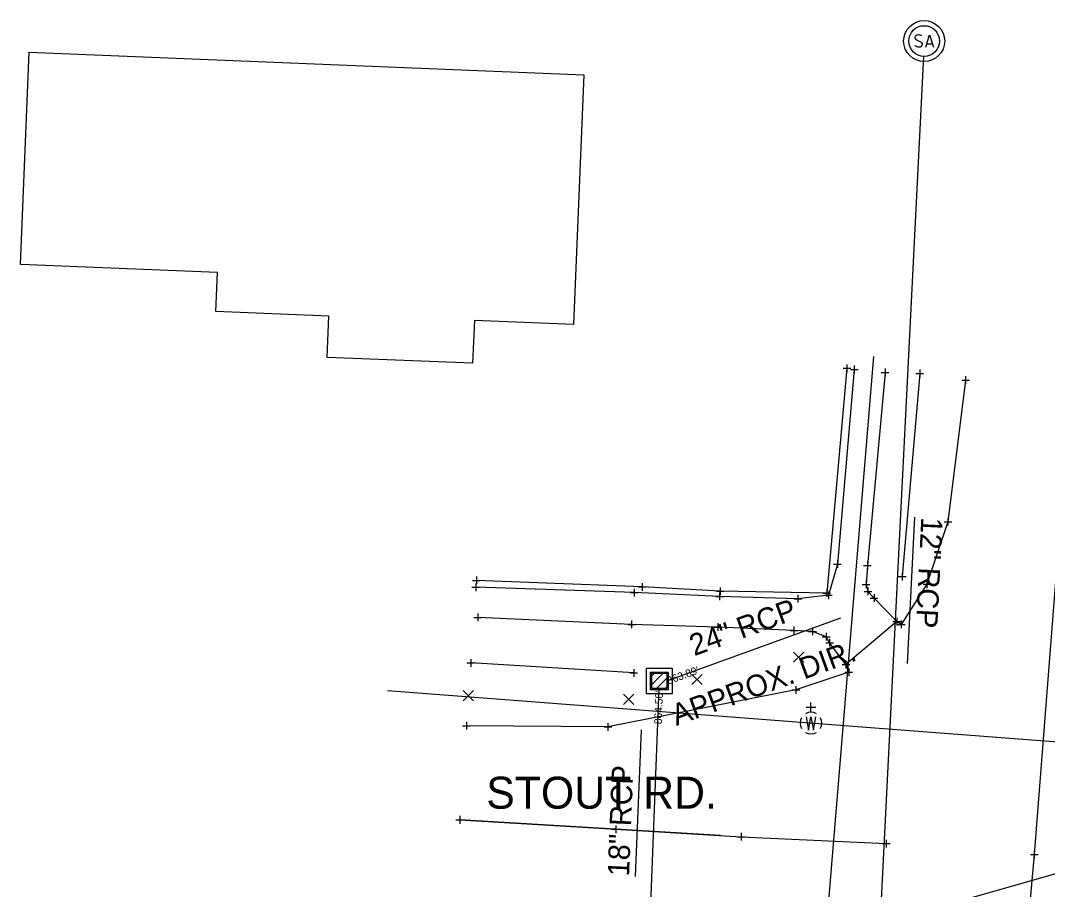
# Model space of a CAD drawing. Extents: x 1380440 to 1381945, y 468756 to 470369.
# Drawn here: x 1381490.3 to 1381624.1, y 470255.4 to 470368.5 of the extents above; entities that cross this region are included whole.
import ezdxf

# ---------------------------------------------------------------- set-up
doc = ezdxf.new("R2010")
doc.units = 0
for name, color, linetype in [('BD_X_Building', 7, 'Continuous'), ('DR_P_Headwall', 7, 'Continuous'), ('GE_P_Driveway_CL', 7, 'Continuous'), ('GK_Drainage_Nodes', 7, 'Continuous'), ('PM_X_CL_Double_Solid', 7, 'Continuous'), ('PM_X_Crosswalk', 7, 'Continuous'), ('PV_P_Curb', 7, 'Continuous'), ('PV_P_Curb_Ramp', 7, 'Continuous'), ('PV_P_EOP', 7, 'Continuous'), ('PV_P_Joint', 7, 'Continuous'), ('RW_P_Const_Limits', 7, 'Continuous'), ('RW_P_Esmt_TMP', 7, 'Continuous'), ('RW_X_CL', 7, 'Continuous'), ('SC_Scratch1', 7, 'Continuous'), ('SC_Shading1', 7, 'Continuous'), ('SH_Named_Boundary', 7, 'Continuous'), ('UT_X_Gas', 7, 'Continuous'), ('UT_X_Sanitary_Line', 7, 'Continuous'), ('UT_X_Sanitary_Text', 7, 'Continuous'), ('UT_X_Water', 7, 'Continuous'), ('X-CL', 7, 'Continuous'), ('X-SUBDIVISION', 7, 'Continuous')]:
    doc.layers.add(name, color=color, linetype=linetype)

msp = doc.modelspace()

# ---------------------------------------------------------------- linework, layer by layer
at = {"layer": 'BD_X_Building'}
msp.add_lwpolyline([(1381490.34, 470336.77), (1381491.47, 470364.43), (1381563.68, 470361.48), (1381562.35, 470328.97), (1381549.43, 470329.5), (1381549.2, 470323.92), (1381530.28, 470324.69), (1381530.5, 470330.07), (1381515.76, 470330.67), (1381515.97, 470335.73)], close=True, dxfattribs=at)
at = {"layer": 'DR_P_Headwall'}
for points in [[(1381598.9, 470323.13), (1381596.7, 470297.78), (1381595.54, 470293.73), (1381591.57, 470293.27), (1381581.37, 470293.57), (1381570.24, 470294.06), (1381549.62, 470294.77)], [(1381602.92, 470322.73), (1381600.62, 470297.61), (1381600.44, 470295.13), (1381600.68, 470294.22), (1381601.47, 470293.36), (1381604.44, 470290.29), (1381597.81, 470284.69), (1381595.69, 470287.54), (1381595.24, 470288.31), (1381593.46, 470289.01), (1381591.05, 470289.15), (1381581.13, 470289.58), (1381569.91, 470289.93), (1381549.88, 470290.83)]]:
    msp.add_lwpolyline(points, dxfattribs=at)
at = {"layer": 'GE_P_Driveway_CL'}
for p, q in [((1381590.99, 470284.99), (1381592.32, 470286.32)), ((1381590.99, 470286.32), (1381592.32, 470284.99)), ((1381577.75, 470282.09), (1381579.09, 470283.42)), ((1381577.75, 470283.42), (1381579.09, 470282.09)), ((1381547.97, 470279.98), (1381549.3, 470281.31)), ((1381547.97, 470281.31), (1381549.3, 470279.98)), ((1381568.86, 470279.49), (1381570.2, 470280.83)), ((1381568.86, 470280.83), (1381570.2, 470279.49))]:
    msp.add_line(p, q, dxfattribs=at)
at = {"layer": 'GK_Drainage_Nodes'}
msp.add_lwpolyline([(1381597.94, 470323.28), (1381595.32, 470294.01), (1381581.44, 470294.24), (1381571.27, 470294.81), (1381549.69, 470295.66)], dxfattribs=at)
at = {"layer": 'PM_X_CL_Double_Solid'}
msp.add_line((1381581.5, 470262.44), (1381547.54, 470264.48), dxfattribs=at)
at = {"layer": 'PM_X_Crosswalk'}
msp.add_line((1381638.41, 470261.25), (1381586.42, 470246.45), dxfattribs=at)
at = {"layer": 'PV_P_Curb'}
for points in [[(1381607.42, 470322.6), (1381605.14, 470296.15)], [(1381570.18, 470283.61), (1381548.95, 470284.92)]]:
    msp.add_lwpolyline(points, dxfattribs=at)
at = {"layer": 'PV_P_Curb_Ramp'}
for p, q in [((1381608, 470367.88), (1381608, 470367.88)), ((1381608, 470365.88), (1381608, 470365.88)), ((1381608, 470365.88), (1381608, 470365.88)), ((1381608, 470365.88), (1381608, 470365.88)), ((1381608, 470363.88), (1381608, 470363.88)), ((1381573.51, 470284.22), (1381573.51, 470284.22)), ((1381573.51, 470283.56), (1381573.51, 470283.56)), ((1381572.52, 470282.56), (1381572.52, 470282.56)), ((1381573.51, 470282.56), (1381573.51, 470282.56)), ((1381573.51, 470282.56), (1381573.51, 470282.56)), ((1381573.51, 470282.56), (1381573.51, 470282.56)), ((1381574.51, 470282.56), (1381574.51, 470282.56)), ((1381573.51, 470281.56), (1381573.51, 470281.56)), ((1381573.51, 470280.89), (1381573.51, 470280.89))]:
    msp.add_line(p, q, dxfattribs=at)
msp.add_circle((1381608, 470365.88), 2, dxfattribs=at)
at = {"layer": 'PV_P_EOP'}
for points in [[(1381607.67, 470366.57), (1381607.64, 470366.59), (1381607.61, 470366.62), (1381607.49, 470366.66), (1381607.35, 470366.68), (1381607.25, 470366.68), (1381607.22, 470366.68), (1381607.05, 470366.65), (1381606.91, 470366.57), (1381606.83, 470366.47), (1381606.8, 470366.37), (1381606.8, 470366.29), (1381606.83, 470366.19), (1381606.93, 470366.1), (1381607.62, 470365.73), (1381607.68, 470365.68), (1381607.71, 470365.62), (1381607.73, 470365.55), (1381607.73, 470365.47), (1381607.72, 470365.4), (1381607.71, 470365.35), (1381607.68, 470365.28), (1381607.66, 470365.23), (1381607.63, 470365.2), (1381607.59, 470365.16), (1381607.56, 470365.13), (1381607.51, 470365.11), (1381607.47, 470365.1), (1381607.35, 470365.08), (1381607.18, 470365.08), (1381607.06, 470365.11), (1381606.9, 470365.2), (1381606.8, 470365.27)], [(1381608.21, 470365.08), (1381608.71, 470366.68), (1381609.21, 470365.08)], [(1381609.08, 470365.46), (1381608.34, 470365.46)]]:
    msp.add_lwpolyline(points, dxfattribs=at)
for radius in [2.67, 2]:
    msp.add_circle((1381608, 470365.88), radius, dxfattribs=at)
at = {"layer": 'PV_P_Joint'}
for p, q in [((1381572.37, 470281.94), (1381574.13, 470283.7)), ((1381572.37, 470283.07), (1381573, 470283.7)), ((1381572.97, 470281.41), (1381574.66, 470283.1)), ((1381574.1, 470281.41), (1381574.66, 470281.97))]:
    msp.add_line(p, q, dxfattribs=at)
for points in [[(1381571.85, 470284.22), (1381575.18, 470284.22), (1381575.18, 470280.89), (1381571.85, 470280.89)], [(1381572.37, 470283.7), (1381574.66, 470283.7), (1381574.66, 470281.41), (1381572.37, 470281.41)], [(1381572.52, 470283.56), (1381574.51, 470283.56), (1381574.51, 470281.56), (1381572.52, 470281.56)]]:
    msp.add_lwpolyline(points, close=True, dxfattribs=at)
at = {"layer": 'RW_P_Const_Limits'}
for p, q in [((1381593.9, 470279.11), (1381592.63, 470279.11)), ((1381593.26, 470278.48), (1381593.26, 470279.75)), ((1381593.26, 470277.08), (1381593.26, 470277.08))]:
    msp.add_line(p, q, dxfattribs=at)
msp.add_lwpolyline([(1381592.63, 470277.9), (1381592.94, 470276.17), (1381593.26, 470277.9), (1381593.58, 470276.17), (1381593.9, 470277.9)], dxfattribs=at)
for start, end in [(150.0184, 209.9816), (60.0184, 120.0157), (330.0184, 29.9816), (239.9843, 299.9816)]:
    msp.add_arc((1381593.26, 470277.08), 1.4, start, end, dxfattribs=at)
at = {"layer": 'RW_P_Esmt_TMP'}
msp.add_lwpolyline([(1381613.39, 470321.73), (1381611.1, 470303.3), (1381608.36, 470295.15), (1381605.01, 470289.92), (1381604.44, 470290.29), (1381597.81, 470284.69), (1381598.17, 470283.7), (1381591.29, 470281.39), (1381566.82, 470276.57), (1381548.39, 470276.73)], dxfattribs=at)
at = {"layer": 'RW_X_CL'}
for p, q in [((1381605.85, 470284.84), (1381606.8, 470303.9)), ((1381571.15, 470276.19), (1381570.39, 470257.11))]:
    msp.add_line(p, q, dxfattribs=at)
at = {"layer": 'SC_Shading1'}
for points in [[(1381627.41, 470324.23), (1381625.02, 470294.42), (1381622.34, 470259.95), (1381618.76, 470220.14), (1381616.92, 470200.19), (1381615.1, 470178.83), (1381610.95, 470124.78), (1381606.49, 470071.23), (1381602.26, 470019.36), (1381598.18, 469969.8), (1381595.01, 469928.06), (1381590.91, 469878.81), (1381589.36, 469859.11), (1381585.99, 469815.58)], [(1381547.54, 470264.48), (1381567.85, 470263.26), (1381584.18, 470262.28), (1381603.07, 470261.39)]]:
    msp.add_lwpolyline(points, dxfattribs=at)
at = {"layer": 'SH_Named_Boundary'}
for p, q in [((1381597.44, 470323.28), (1381598.44, 470323.28)), ((1381597.94, 470323.78), (1381597.94, 470322.78)), ((1381597.94, 470323.28), (1381597.94, 470323.28)), ((1381598.9, 470323.63), (1381598.9, 470322.63)), ((1381598.4, 470323.13), (1381599.4, 470323.13)), ((1381598.9, 470323.13), (1381598.9, 470323.13)), ((1381602.42, 470322.73), (1381603.42, 470322.73)), ((1381602.92, 470323.23), (1381602.92, 470322.23)), ((1381602.92, 470322.73), (1381602.92, 470322.73)), ((1381606.92, 470322.6), (1381607.92, 470322.6)), ((1381607.42, 470323.1), (1381607.42, 470322.1)), ((1381607.42, 470322.6), (1381607.42, 470322.6)), ((1381613.39, 470322.23), (1381613.39, 470321.23)), ((1381612.89, 470321.73), (1381613.89, 470321.73)), ((1381613.39, 470321.73), (1381613.39, 470321.73)), ((1381610.6, 470303.3), (1381611.6, 470303.3)), ((1381610.6, 470303.3), (1381611.6, 470303.3)), ((1381611.1, 470303.8), (1381611.1, 470302.8)), ((1381611.1, 470303.8), (1381611.1, 470302.8)), ((1381611.1, 470303.3), (1381611.1, 470303.3)), ((1381611.1, 470303.3), (1381611.1, 470303.3)), ((1381596.7, 470298.28), (1381596.7, 470297.28)), ((1381596.7, 470298.28), (1381596.7, 470297.28)), ((1381600.62, 470298.11), (1381600.62, 470297.11)), ((1381596.2, 470297.78), (1381597.2, 470297.78)), ((1381596.2, 470297.78), (1381597.2, 470297.78)), ((1381596.7, 470297.78), (1381596.7, 470297.78)), ((1381596.7, 470297.78), (1381596.7, 470297.78)), ((1381600.12, 470297.61), (1381601.12, 470297.61)), ((1381600.62, 470297.61), (1381600.62, 470297.61)), ((1381605.14, 470296.65), (1381605.14, 470295.65)), ((1381549.19, 470295.66), (1381550.19, 470295.66)), ((1381549.62, 470295.27), (1381549.62, 470294.27)), ((1381549.69, 470296.16), (1381549.69, 470295.16)), ((1381549.69, 470295.66), (1381549.69, 470295.66)), ((1381571.27, 470295.31), (1381571.27, 470294.31)), ((1381600.44, 470295.63), (1381600.44, 470294.63)), ((1381600.44, 470295.63), (1381600.44, 470294.63)), ((1381604.64, 470296.15), (1381605.64, 470296.15)), ((1381605.14, 470296.15), (1381605.14, 470296.15)), ((1381608.36, 470295.65), (1381608.36, 470294.65)), ((1381549.12, 470294.77), (1381550.12, 470294.77)), ((1381549.62, 470294.77), (1381549.62, 470294.77)), ((1381569.74, 470294.06), (1381570.74, 470294.06)), ((1381570.24, 470294.56), (1381570.24, 470293.56)), ((1381570.24, 470294.06), (1381570.24, 470294.06)), ((1381570.77, 470294.81), (1381571.77, 470294.81)), ((1381571.27, 470294.81), (1381571.27, 470294.81)), ((1381580.94, 470294.24), (1381581.94, 470294.24)), ((1381581.37, 470294.07), (1381581.37, 470293.07)), ((1381581.44, 470294.74), (1381581.44, 470293.74)), ((1381581.44, 470294.24), (1381581.44, 470294.24)), ((1381594.82, 470294.01), (1381595.82, 470294.01)), ((1381595.32, 470294.51), (1381595.32, 470293.51)), ((1381595.32, 470294.01), (1381595.32, 470294.01)), ((1381595.54, 470294.23), (1381595.54, 470293.23)), ((1381599.94, 470295.13), (1381600.94, 470295.13)), ((1381599.94, 470295.13), (1381600.94, 470295.13)), ((1381600.18, 470294.22), (1381601.18, 470294.22)), ((1381600.44, 470295.13), (1381600.44, 470295.13)), ((1381600.44, 470295.13), (1381600.44, 470295.13)), ((1381600.68, 470294.72), (1381600.68, 470293.72)), ((1381600.68, 470294.22), (1381600.68, 470294.22)), ((1381601.47, 470293.86), (1381601.47, 470292.86)), ((1381601.47, 470293.86), (1381601.47, 470292.86)), ((1381607.86, 470295.15), (1381608.86, 470295.15)), ((1381608.36, 470295.15), (1381608.36, 470295.15)), ((1381580.87, 470293.57), (1381581.87, 470293.57)), ((1381581.37, 470293.57), (1381581.37, 470293.57)), ((1381591.07, 470293.27), (1381592.07, 470293.27)), ((1381591.07, 470293.27), (1381592.07, 470293.27)), ((1381591.57, 470293.77), (1381591.57, 470292.77)), ((1381591.57, 470293.77), (1381591.57, 470292.77)), ((1381591.57, 470293.27), (1381591.57, 470293.27)), ((1381591.57, 470293.27), (1381591.57, 470293.27)), ((1381595.04, 470293.73), (1381596.04, 470293.73)), ((1381595.54, 470293.73), (1381595.54, 470293.73)), ((1381600.97, 470293.36), (1381601.97, 470293.36)), ((1381600.97, 470293.36), (1381601.97, 470293.36)), ((1381601.47, 470293.36), (1381601.47, 470293.36)), ((1381601.47, 470293.36), (1381601.47, 470293.36)), ((1381549.88, 470291.33), (1381549.88, 470290.33)), ((1381549.38, 470290.83), (1381550.38, 470290.83)), ((1381549.88, 470290.83), (1381549.88, 470290.83)), ((1381569.41, 470289.93), (1381570.41, 470289.93)), ((1381569.91, 470290.43), (1381569.91, 470289.43)), ((1381569.91, 470289.93), (1381569.91, 470289.93)), ((1381581.13, 470290.08), (1381581.13, 470289.08)), ((1381603.94, 470290.29), (1381604.94, 470290.29)), ((1381603.94, 470290.29), (1381604.94, 470290.29)), ((1381604.44, 470290.79), (1381604.44, 470289.79)), ((1381604.44, 470290.79), (1381604.44, 470289.79)), ((1381604.44, 470290.29), (1381604.44, 470290.29)), ((1381604.44, 470290.29), (1381604.44, 470290.29)), ((1381604.51, 470289.92), (1381605.51, 470289.92)), ((1381604.51, 470289.92), (1381605.51, 470289.92)), ((1381605.01, 470290.42), (1381605.01, 470289.42)), ((1381605.01, 470290.42), (1381605.01, 470289.42)), ((1381605.01, 470289.92), (1381605.01, 470289.92)), ((1381605.01, 470289.92), (1381605.01, 470289.92)), ((1381580.63, 470289.58), (1381581.63, 470289.58)), ((1381581.13, 470289.58), (1381581.13, 470289.58)), ((1381590.55, 470289.15), (1381591.55, 470289.15)), ((1381591.05, 470289.65), (1381591.05, 470288.65)), ((1381591.05, 470289.15), (1381591.05, 470289.15)), ((1381592.96, 470289.01), (1381593.96, 470289.01)), ((1381592.96, 470289.01), (1381593.96, 470289.01)), ((1381593.46, 470289.51), (1381593.46, 470288.51)), ((1381593.46, 470289.51), (1381593.46, 470288.51)), ((1381593.46, 470289.01), (1381593.46, 470289.01)), ((1381593.46, 470289.01), (1381593.46, 470289.01)), ((1381595.24, 470288.81), (1381595.24, 470287.81)), ((1381594.74, 470288.31), (1381595.74, 470288.31)), ((1381595.19, 470287.54), (1381596.19, 470287.54)), ((1381595.19, 470287.54), (1381596.19, 470287.54)), ((1381595.24, 470288.31), (1381595.24, 470288.31)), ((1381595.69, 470288.04), (1381595.69, 470287.04)), ((1381595.69, 470288.04), (1381595.69, 470287.04)), ((1381595.69, 470287.54), (1381595.69, 470287.54)), ((1381595.69, 470287.54), (1381595.69, 470287.54)), ((1381548.45, 470284.92), (1381549.45, 470284.92)), ((1381548.95, 470285.42), (1381548.95, 470284.42)), ((1381548.95, 470284.92), (1381548.95, 470284.92)), ((1381597.31, 470284.69), (1381598.31, 470284.69)), ((1381597.31, 470284.69), (1381598.31, 470284.69)), ((1381597.81, 470285.19), (1381597.81, 470284.19)), ((1381597.81, 470285.19), (1381597.81, 470284.19)), ((1381597.81, 470284.69), (1381597.81, 470284.69)), ((1381597.81, 470284.69), (1381597.81, 470284.69)), ((1381569.68, 470283.61), (1381570.68, 470283.61)), ((1381570.18, 470284.11), (1381570.18, 470283.11)), ((1381570.18, 470283.61), (1381570.18, 470283.61)), ((1381597.67, 470283.7), (1381598.67, 470283.7)), ((1381598.17, 470284.2), (1381598.17, 470283.2)), ((1381598.17, 470283.7), (1381598.17, 470283.7)), ((1381591.29, 470281.89), (1381591.29, 470280.89)), ((1381590.79, 470281.39), (1381591.79, 470281.39)), ((1381591.29, 470281.39), (1381591.29, 470281.39)), ((1381547.89, 470276.73), (1381548.89, 470276.73)), ((1381548.39, 470277.23), (1381548.39, 470276.23)), ((1381548.39, 470276.73), (1381548.39, 470276.73)), ((1381566.32, 470276.57), (1381567.32, 470276.57)), ((1381566.82, 470277.07), (1381566.82, 470276.07)), ((1381566.82, 470276.57), (1381566.82, 470276.57)), ((1381547.04, 470264.48), (1381548.04, 470264.48)), ((1381547.54, 470264.98), (1381547.54, 470263.98)), ((1381547.54, 470264.48), (1381547.54, 470264.48)), ((1381567.35, 470263.26), (1381568.35, 470263.26)), ((1381567.85, 470263.76), (1381567.85, 470262.76)), ((1381567.85, 470263.26), (1381567.85, 470263.26)), ((1381583.68, 470262.28), (1381584.68, 470262.28)), ((1381584.18, 470262.78), (1381584.18, 470261.78)), ((1381584.18, 470262.28), (1381584.18, 470262.28)), ((1381603.07, 470261.89), (1381603.07, 470260.89)), ((1381602.57, 470261.39), (1381603.57, 470261.39)), ((1381603.07, 470261.39), (1381603.07, 470261.39)), ((1381622.34, 470260.45), (1381622.34, 470259.45)), ((1381621.84, 470259.95), (1381622.84, 470259.95)), ((1381622.34, 470259.95), (1381622.34, 470259.95))]:
    msp.add_line(p, q, dxfattribs=at)
at = {"layer": 'UT_X_Gas'}
msp.add_line((1381594.27, 470237.89), (1381601.45, 470324.79), dxfattribs=at)
at = {"layer": 'UT_X_Sanitary_Line'}
msp.add_line((1381607.9, 470363.89), (1381601.16, 470229.04), dxfattribs=at)
at = {"layer": 'UT_X_Sanitary_Text'}
msp.add_line((1381605.85, 470284.84), (1381606.8, 470303.9), dxfattribs=at)
at = {"layer": 'UT_X_Water'}
msp.add_line((1381635.18, 470273.84), (1381538.11, 470281.27), dxfattribs=at)
at = {"layer": 'X-CL'}
for p, q in [((1381574.51, 470282.56), (1381597.14, 470290.77)), ((1381572.17, 470247.58), (1381573.51, 470281.56))]:
    msp.add_line(p, q, dxfattribs=at)

# ---------------------------------------------------------------- texts
at = {"layer": 'RW_X_CL'}
for s, rotation, p in [('12" RCP', 267.1364, (1381607.63, 470303.92)), ('24" RCP', 19.9584, (1381578.06, 470285.78)), ('APPROX. DIR.', 19.9584, (1381575.73, 470276.7)), ('18" RCP', 87.7266, (1381569.57, 470257.09))]:
    msp.add_text(s, height=2.8, rotation=rotation, dxfattribs=at).set_placement(p)
at = {"layer": 'SC_Scratch1'}
for s, rotation, p in [("863.89'", 19.9584, (1381574.69, 470282.09)), ("864.50'", 87.7266, (1381573.83, 470276.91))]:
    msp.add_text(s, height=1, rotation=rotation, dxfattribs=at).set_placement(p)
at = {"layer": 'UT_X_Sanitary_Text'}
msp.add_text('12" RCP', height=2.8, rotation=267.1364, dxfattribs=at).set_placement((1381607.63, 470303.92))
at = {"layer": 'X-SUBDIVISION'}
msp.add_text('STOUT RD.', height=4.167, dxfattribs=at).set_placement((1381550.98, 470265.93))

doc.saveas('drawing.dxf')
